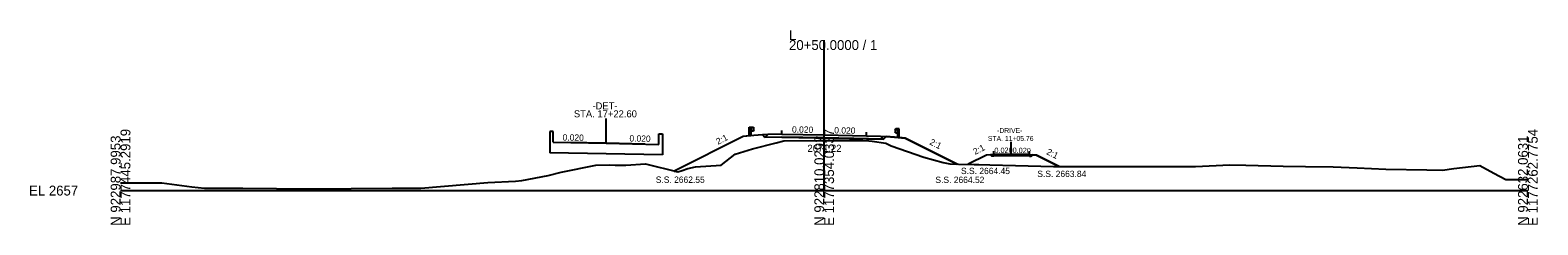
# Model space of a CAD drawing. Extents: x -26 to 1403, y -10 to 9563.
# Drawn here: x 974.3 to 1402.8, y 490.3 to 545.5 of the extents above; entities that cross this region are included whole.
import ezdxf

# ---------------------------------------------------------------- set-up
doc = ezdxf.new("R2010")
doc.units = 0
for name, color, linetype in [('Exist Cross Section Cell', 7, 'Continuous'), ('Exist XS Center Line Elevation Label', 7, 'Continuous'), ('Exist XS Ground Line', 7, 'Continuous'), ('Prop XS Bridge', 7, 'Continuous'), ('Prop XS Dump Level', 7, 'Continuous'), ('Prop XS Earthwork Shape', 7, 'Continuous'), ('Prop XS EOT Tick Mark', 7, 'Continuous'), ('Prop XS Finish Grade', 7, 'Continuous'), ('Prop XS Finish Grade Earthwork', 7, 'Continuous'), ('Prop XS Finish Grade Paved Shoulder', 7, 'Continuous'), ('Prop XS Finish Grade Pavement', 7, 'Continuous'), ('Prop XS Guardrail', 7, 'Continuous'), ('Prop XS Pvmt Edge Slope', 7, 'Continuous'), ('Prop XS SE Text', 7, 'Continuous'), ('Prop XS Side Slope Text', 7, 'Continuous'), ('Prop XS SS Elevation Text', 7, 'Continuous'), ('Prop XS Subgrade Earthwork', 7, 'Continuous'), ('Prop XS Vertical Lines', 7, 'Continuous'), ('Prop XS Vertical Lines Alignments', 7, 'Continuous')]:
    doc.layers.add(name, color=color, linetype=linetype)

msp = doc.modelspace()

# ---------------------------------------------------------------- linework, layer by layer
at = {"layer": 'Exist Cross Section Cell'}
for p, q in [((1200, 500), (1200, 542.66)), ((1000, 500), (1200, 500)), ((1200, 500), (1400, 500))]:
    msp.add_line(p, q, dxfattribs=at)
at = {"layer": 'Exist XS Ground Line'}
for p, q in [((1170.76, 507.18), (1174.73, 510.28)), ((1174.73, 510.28), (1179.64, 511.82)), ((1179.64, 511.82), (1186.36, 513.52)), ((1186.36, 513.52), (1188.56, 514.15)), ((1188.56, 514.15), (1198.37, 514.21)), ((1198.37, 514.21), (1199.6, 514.22)), ((1199.6, 514.22), (1200, 514.22)), ((1200, 514.22), (1211, 514.21)), ((1211, 514.21), (1212.73, 514.06)), ((1212.73, 514.06), (1213.62, 514.03)), ((1213.62, 514.03), (1217.49, 513.42)), ((1217.49, 513.42), (1219.06, 512.73)), ((1219.06, 512.73), (1228.28, 509.49)), ((1125.24, 505.18), (1135.11, 507.23)), ((1135.11, 507.23), (1138.92, 507.26)), ((1138.92, 507.26), (1140.62, 507.22)), ((1140.62, 507.22), (1143.58, 507.17)), ((1143.58, 507.17), (1149.22, 507.55)), ((1149.22, 507.55), (1158.42, 505.28)), ((1158.42, 505.28), (1159.59, 505.7)), ((1159.59, 505.7), (1161.27, 506.27)), ((1161.27, 506.27), (1163.45, 506.74)), ((1163.45, 506.74), (1170.76, 507.18)), ((1228.28, 509.49), (1233.85, 508)), ((1233.85, 508), (1235.74, 507.56)), ((1235.74, 507.56), (1238.17, 507.51)), ((1238.17, 507.51), (1247.04, 507.31)), ((1247.04, 507.31), (1254.38, 507.12)), ((1254.38, 507.12), (1265.13, 506.85)), ((1265.13, 506.85), (1291.07, 506.79)), ((1291.07, 506.79), (1293.9, 506.78)), ((1293.9, 506.78), (1299.47, 506.8)), ((1299.47, 506.8), (1305.55, 506.83)), ((1305.55, 506.83), (1315.28, 507.3)), ((1315.28, 507.3), (1319.83, 507.19)), ((1319.83, 507.19), (1330.47, 506.9)), ((1330.47, 506.9), (1336.81, 506.8)), ((1336.81, 506.8), (1344.7, 506.75)), ((1344.7, 506.75), (1351.53, 506.41)), ((1351.53, 506.41), (1359.61, 506.05)), ((1359.61, 506.05), (1371.25, 505.91)), ((1371.25, 505.91), (1375.77, 505.82)), ((1375.77, 505.82), (1378.93, 506.28)), ((1378.93, 506.28), (1386.34, 507.07)), ((1386.34, 507.07), (1390.29, 504.97)), ((1000, 502.19), (1003.19, 502.19)), ((1003.19, 502.19), (1004.09, 502.19)), ((1004.09, 502.19), (1006.18, 502.18)), ((1006.18, 502.18), (1009.35, 502.17)), ((1009.35, 502.17), (1011.7, 502.17)), ((1011.7, 502.17), (1020.24, 501.03)), ((1085.31, 500.67), (1104.4, 502.29)), ((1104.4, 502.29), (1112.29, 502.7)), ((1112.29, 502.7), (1114.08, 502.84)), ((1114.08, 502.84), (1121.51, 504.28)), ((1121.51, 504.28), (1125.24, 505.18)), ((1390.29, 504.97), (1393.7, 503.13)), ((1393.7, 503.13), (1396.73, 503.14)), ((1396.73, 503.14), (1400, 503.14)), ((1020.24, 501.03), (1023.9, 500.65)), ((1023.9, 500.65), (1034.8, 500.66)), ((1034.8, 500.66), (1053.91, 500.53)), ((1053.91, 500.53), (1077.2, 500.67)), ((1077.2, 500.67), (1080.19, 500.67)), ((1080.19, 500.67), (1085.31, 500.67))]:
    msp.add_line(p, q, dxfattribs=at)
at = {"layer": 'Prop XS Bridge'}
for p, q in [((1122, 516.71), (1122, 513.71)), ((1123, 516.71), (1122, 516.71)), ((1123, 513.71), (1123, 516.71)), ((1153, 513.11), (1153, 516.11)), ((1153, 516.11), (1154, 516.11)), ((1154, 516.11), (1154, 513.11)), ((1122, 513.71), (1122, 510.71)), ((1154, 510.12), (1122, 510.71)), ((1123, 513.71), (1138, 513.41)), ((1138, 513.41), (1153, 513.11)), ((1154, 513.11), (1154, 510.11))]:
    msp.add_line(p, q, dxfattribs=at)
at = {"layer": 'Prop XS Dump Level'}
for p, q in [((1188, 516.01), (1200, 515.77)), ((1200, 515.77), (1212, 515.53)), ((1138, 513.41), (1127, 513.63)), ((1149, 513.19), (1138, 513.41)), ((1248.17, 510.22), (1253.17, 510.32)), ((1253.17, 510.32), (1248.17, 510.22)), ((1253.17, 510.32), (1258.36, 510.22)), ((1258.36, 510.22), (1253.17, 510.32))]:
    msp.add_line(p, q, dxfattribs=at)
at = {"layer": 'Prop XS Earthwork Shape'}
for p, q in [((1177, 515.37), (1157.36, 505.55)), ((1182.43, 515.8), (1180, 515.61)), ((1183.15, 515.08), (1182.43, 515.8)), ((1188, 515.17), (1183.15, 515.08)), ((1200, 514.93), (1188, 515.17)), ((1200, 514.22), (1200, 514.93)), ((1216.85, 514.6), (1200, 514.93)), ((1200, 514.93), (1200, 514.22)), ((1217.57, 515.32), (1216.85, 514.6)), ((1220, 515.13), (1217.57, 515.32)), ((1220.82, 515.06), (1220, 515.13)), ((1237.75, 507.52), (1223, 514.89)), ((1170.76, 507.18), (1174.73, 510.28)), ((1174.73, 510.28), (1179.64, 511.82)), ((1179.64, 511.82), (1186.36, 513.52)), ((1186.36, 513.52), (1188.56, 514.15)), ((1188.56, 514.15), (1198.37, 514.21)), ((1198.37, 514.21), (1199.6, 514.22)), ((1199.6, 514.22), (1200, 514.22)), ((1200, 514.22), (1200, 514.22)), ((1200, 514.22), (1211, 514.21)), ((1211, 514.21), (1212.73, 514.06)), ((1212.73, 514.06), (1213.62, 514.03)), ((1213.62, 514.03), (1217.49, 513.42)), ((1217.49, 513.42), (1219.06, 512.73)), ((1219.06, 512.73), (1228.28, 509.49)), ((1158.42, 505.28), (1159.59, 505.7)), ((1159.59, 505.7), (1161.27, 506.27)), ((1161.27, 506.27), (1163.45, 506.74)), ((1163.45, 506.74), (1170.76, 507.18)), ((1228.28, 509.49), (1233.85, 508)), ((1233.85, 508), (1235.74, 507.56)), ((1235.74, 507.56), (1237.75, 507.52)), ((1157.36, 505.55), (1158.42, 505.28))]:
    msp.add_line(p, q, dxfattribs=at)
for points in [[(1180, 515.61), (1179.18, 515.54), (1178.68, 515.5), (1177, 515.37)], [(1223, 514.89), (1221.32, 515.02), (1220.82, 515.06)]]:
    msp.add_lwpolyline(points, dxfattribs=at)
msp.add_lwpolyline([(1240.94, 507.45), (1247.04, 507.31), (1254.38, 507.12), (1265.13, 506.85), (1266.79, 506.84), (1260.36, 510.06), (1259.3, 510.14), (1258.87, 509.71), (1258.36, 509.72), (1253.17, 509.82), (1248.17, 509.72), (1247.66, 509.71), (1247.22, 510.15), (1246.17, 510.06)], close=True, dxfattribs=at)
at = {"layer": 'Prop XS EOT Tick Mark'}
for p, q in [((1188, 516.01), (1188, 517.01)), ((1212, 515.53), (1212, 516.53)), ((1248.17, 510.22), (1248.17, 511.22)), ((1258.36, 510.22), (1258.36, 511.22))]:
    msp.add_line(p, q, dxfattribs=at)
at = {"layer": 'Prop XS Finish Grade'}
for p, q in [((1184, 515.93), (1182.43, 515.8)), ((1216, 515.45), (1217.57, 515.32)), ((1248.17, 510.22), (1247.22, 510.15)), ((1258.36, 510.22), (1259.3, 510.14))]:
    msp.add_line(p, q, dxfattribs=at)
at = {"layer": 'Prop XS Finish Grade Earthwork'}
for p, q in [((1177, 515.37), (1157.36, 505.55)), ((1180, 515.61), (1177, 515.37)), ((1182.43, 515.8), (1180, 515.61)), ((1217.57, 515.32), (1220, 515.13)), ((1220, 515.13), (1223, 514.89)), ((1223, 514.89), (1237.75, 507.52)), ((1246.17, 510.06), (1240.94, 507.45)), ((1247.22, 510.15), (1246.17, 510.06)), ((1259.3, 510.14), (1260.36, 510.06)), ((1260.36, 510.06), (1266.79, 506.84))]:
    msp.add_line(p, q, dxfattribs=at)
at = {"layer": 'Prop XS Finish Grade Paved Shoulder'}
for p, q in [((1188, 516.01), (1184, 515.93)), ((1212, 515.53), (1216, 515.45))]:
    msp.add_line(p, q, dxfattribs=at)
at = {"layer": 'Prop XS Finish Grade Pavement'}
for p, q in [((1188, 516.01), (1200, 515.77)), ((1200, 515.77), (1212, 515.53)), ((1248.17, 510.22), (1253.17, 510.32)), ((1253.17, 510.32), (1258.36, 510.22))]:
    msp.add_line(p, q, dxfattribs=at)
at = {"layer": 'Prop XS Guardrail'}
for p, q in [((1178.68, 518), (1179.18, 518)), ((1178.68, 515.5), (1178.68, 518)), ((1179.18, 518), (1179.68, 518)), ((1179.18, 518), (1179.18, 515.5)), ((1179.68, 516.87), (1179.18, 516.87)), ((1179.68, 518), (1179.97, 517.8)), ((1179.97, 517.68), (1179.68, 517.48)), ((1179.68, 517.48), (1179.68, 517.39)), ((1179.68, 517.39), (1179.97, 517.19)), ((1179.97, 517.07), (1179.68, 516.87)), ((1179.97, 517.8), (1180, 517.74)), ((1180, 517.74), (1179.97, 517.68)), ((1179.97, 517.19), (1180, 517.13)), ((1180, 517.13), (1179.97, 517.07)), ((1220.03, 517.32), (1220, 517.26)), ((1220, 517.26), (1220.03, 517.2)), ((1220.03, 516.71), (1220, 516.65)), ((1220, 516.65), (1220.03, 516.59)), ((1220.32, 517.52), (1220.03, 517.32)), ((1220.03, 517.2), (1220.32, 517)), ((1220.32, 516.91), (1220.03, 516.71)), ((1220.03, 516.59), (1220.32, 516.39)), ((1220.82, 517.52), (1220.32, 517.52)), ((1220.32, 517), (1220.32, 516.91)), ((1220.32, 516.39), (1220.82, 516.39)), ((1221.32, 517.52), (1220.82, 517.52)), ((1220.82, 517.52), (1220.82, 515.02)), ((1221.32, 515.02), (1221.32, 517.52))]:
    msp.add_line(p, q, dxfattribs=at)
at = {"layer": 'Prop XS Pvmt Edge Slope'}
for p, q in [((1184, 515.93), (1183.15, 515.08)), ((1216, 515.45), (1216.85, 514.6)), ((1248.17, 510.22), (1247.66, 509.71)), ((1258.36, 510.22), (1258.87, 509.71))]:
    msp.add_line(p, q, dxfattribs=at)
at = {"layer": 'Prop XS Subgrade Earthwork'}
for p, q in [((1183.15, 515.08), (1182.43, 515.8)), ((1188, 515.17), (1183.15, 515.08)), ((1188, 515.17), (1216.85, 514.6)), ((1216.85, 514.6), (1217.57, 515.32)), ((1247.66, 509.71), (1247.22, 510.15)), ((1258.87, 509.71), (1259.3, 510.14)), ((1248.17, 509.72), (1247.66, 509.71)), ((1253.17, 509.82), (1248.17, 509.72)), ((1258.36, 509.72), (1253.17, 509.82)), ((1258.36, 509.72), (1258.87, 509.71))]:
    msp.add_line(p, q, dxfattribs=at)
at = {"layer": 'Prop XS Vertical Lines'}
for p, q in [((1138, 513.41), (1138, 520.41)), ((1253.17, 510.32), (1253.17, 513.82))]:
    msp.add_line(p, q, dxfattribs=at)

# ---------------------------------------------------------------- texts
at = {"layer": 'Exist Cross Section Cell'}
for s, p in [('L', (1190, 542.66)), ('20+50.0000 / 1', (1190, 539.86)), ('EL 2657', (974, 498.6))]:
    msp.add_text(s, height=2.8, dxfattribs=at).set_placement(p)
for s, p in [('N 922987.9953', (1000, 490)), ('E 1177445.2919', (1002.8, 490)), ('N 922810.0292', (1200, 490)), ('E 1177354.0337', (1202.8, 490)), ('N 922632.0631', (1400, 490)), ('E 1177262.7754', (1402.8, 490))]:
    msp.add_text(s, height=2.8, rotation=90, dxfattribs=at).set_placement(p)
at = {"layer": 'Exist XS Center Line Elevation Label'}
msp.add_text('2671.22', height=2, dxfattribs=at).set_placement((1195.24, 510.98))
at = {"layer": 'Prop XS Dump Level'}
for s, p in [('Case2', (1180, 515.57)), ('Case2', (1220, 515.09)), ('Case1', (1246.17, 510.02)), ('Case1', (1260.36, 510.02))]:
    msp.add_text(s, height=0.04, dxfattribs=at).set_placement(p)
at = {"layer": 'Prop XS SE Text'}
for height, rotation, p in [(1.8, 358.8542, (1125.64, 514.2)), (1.8, 358.8542, (1144.63, 513.91)), (1.8, 358.8542, (1190.84, 516.45)), (1.8, 358.8542, (1202.84, 516.21)), (1.5, 1.1458, (1248.4, 510.63)), (1.5, 358.8542, (1253.53, 510.69))]:
    msp.add_text('0.020', height=height, rotation=rotation, dxfattribs=at).set_placement(p)
at = {"layer": 'Prop XS Side Slope Text'}
for rotation, p in [(26.5651, (1169.82, 512.96)), (333.4349, (1229.77, 513.18)), (26.5651, (1242.88, 510.1)), (333.4349, (1263, 510.41))]:
    msp.add_text('2:1', height=1.8, rotation=rotation, dxfattribs=at).set_placement(p)
at = {"layer": 'Prop XS SS Elevation Text'}
for s, p in [('S.S. 2664.45', (1238.88, 504.67)), ('S.S. 2663.84', (1260.58, 503.84)), ('S.S. 2662.55', (1152.12, 502.19)), ('S.S. 2664.52', (1231.61, 502.15))]:
    msp.add_text(s, height=1.8, dxfattribs=at).set_placement(p)
at = {"layer": 'Prop XS Vertical Lines'}
for s, p in [('-DET-', (1134.13, 523.01)), ('STA. 17+22.60', (1128.85, 520.76))]:
    msp.add_text(s, height=2, dxfattribs=at).set_placement(p)
at = {"layer": 'Prop XS Vertical Lines Alignments'}
for s, p in [('STA. 11+05.76', (1246.54, 514.07)), ('-DRIVE-', (1249.14, 516.32))]:
    msp.add_text(s, height=1.4, dxfattribs=at).set_placement(p)

doc.saveas('drawing.dxf')
